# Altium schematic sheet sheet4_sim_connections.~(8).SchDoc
size A3; Author: Mauri Shadi; CompanyName: BFH; DrawnBy: Mauri Shadi; SheetNumber: 2; SheetTotal: 4
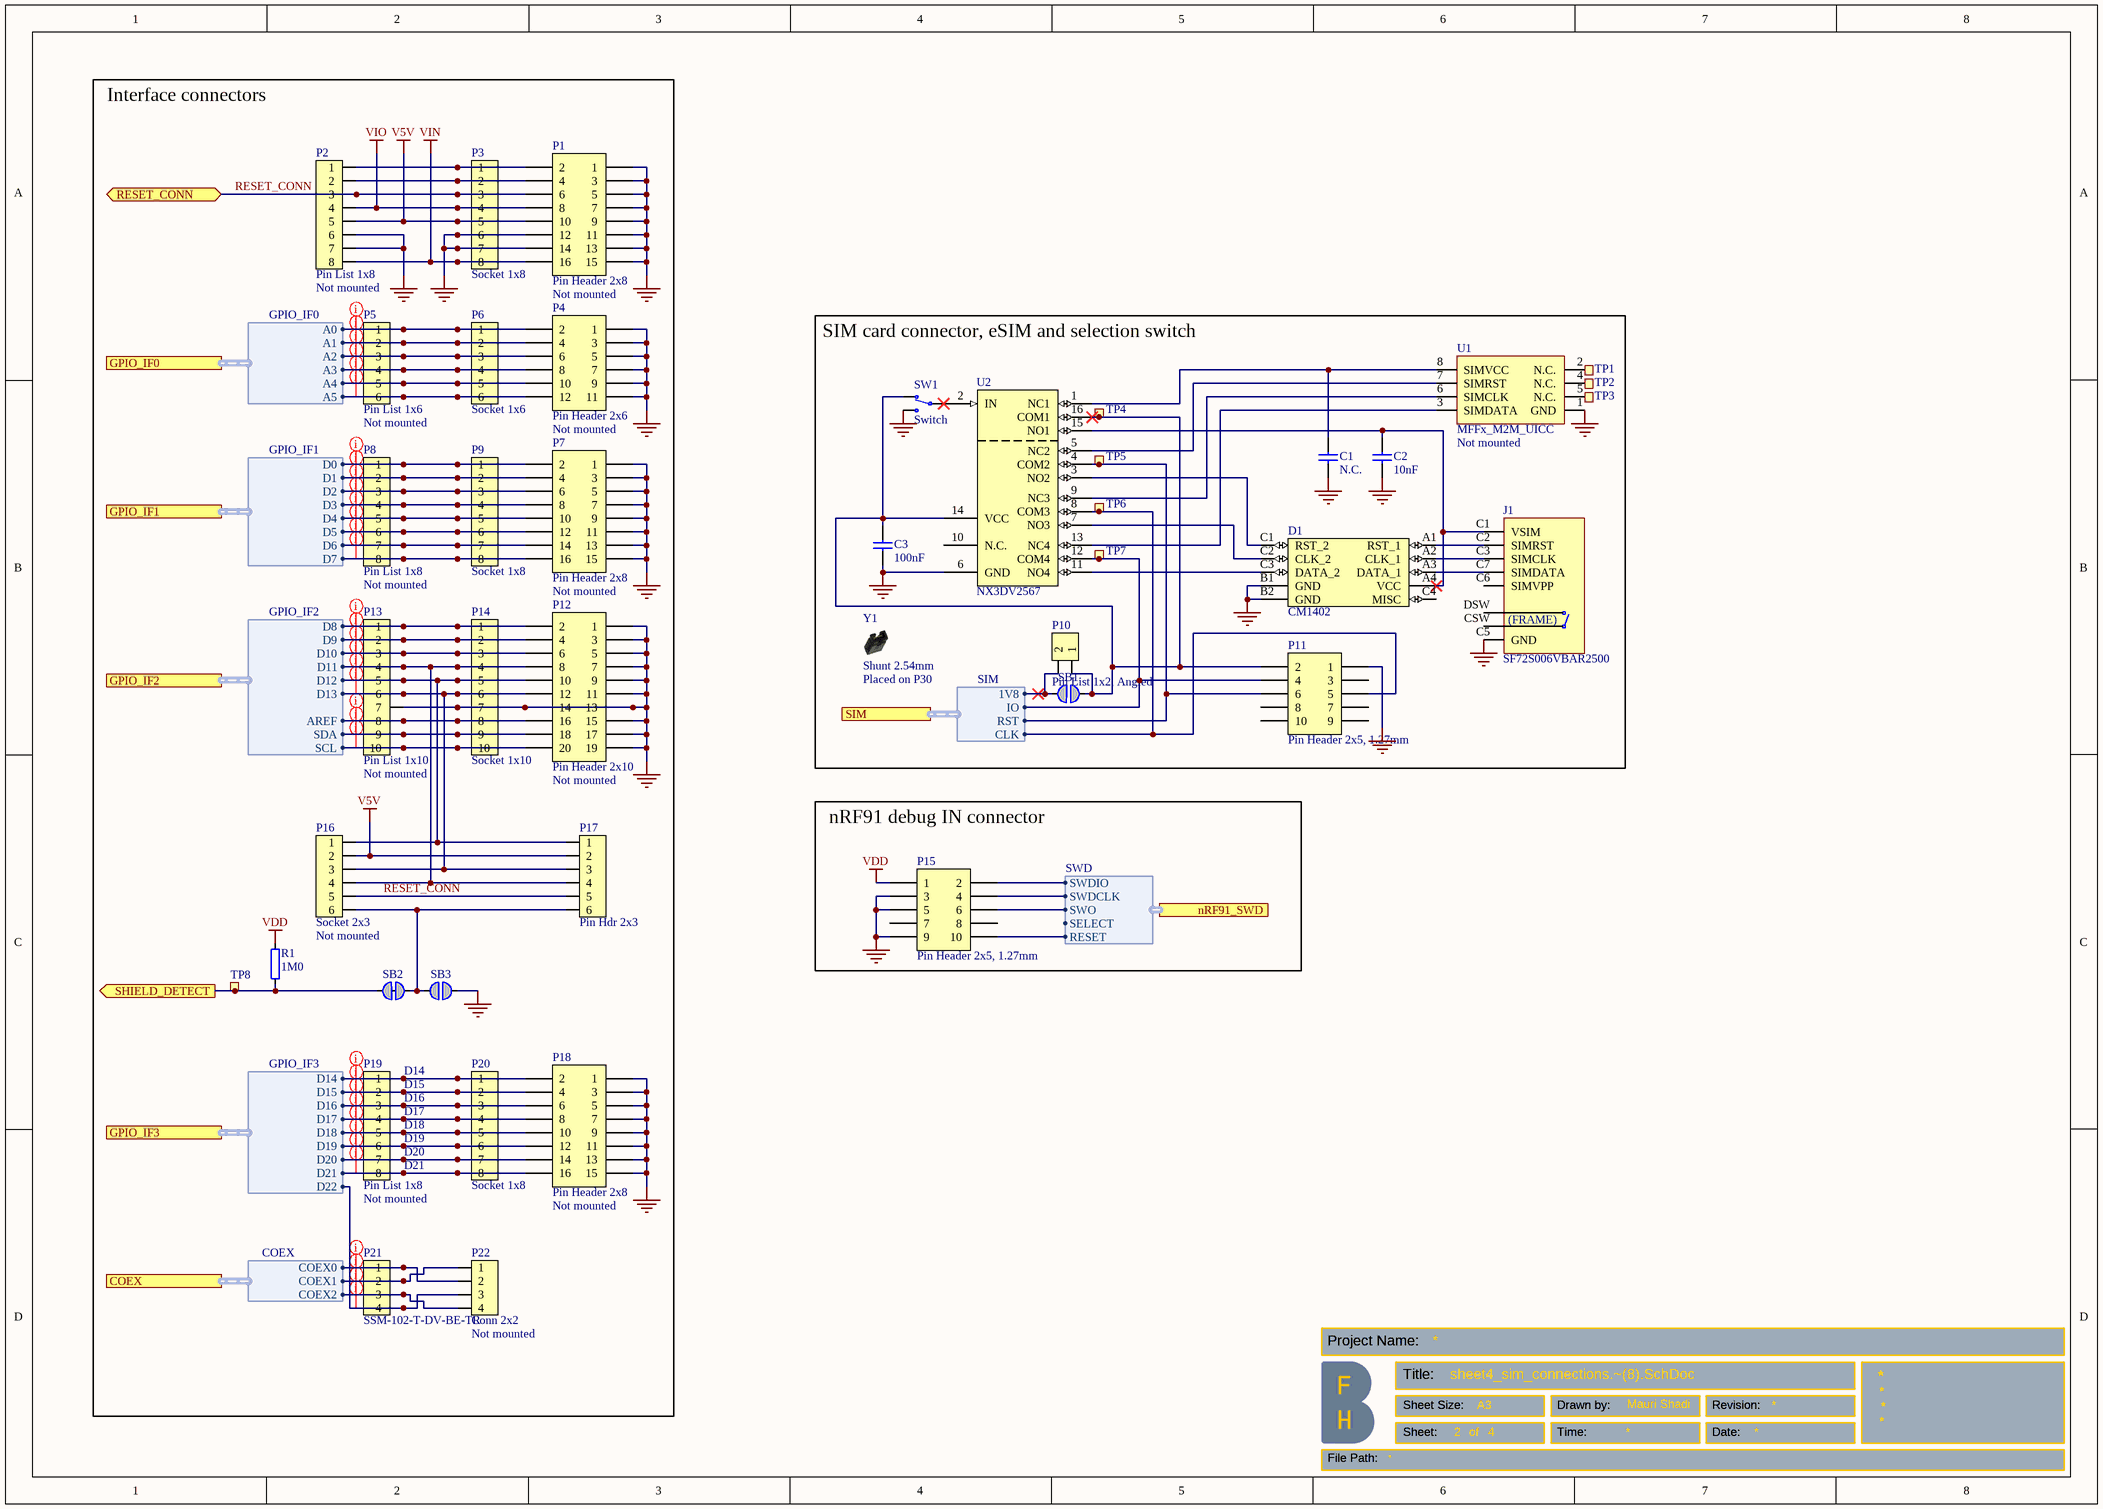
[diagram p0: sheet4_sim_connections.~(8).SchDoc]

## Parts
C1  N.C.  [CAPC0603X03L_C_NC]
C2  10nF  [CAPC0603X03L_C]
C3  100nF  [CAPC0603X03L_C]
D1  CM1402  [CM1402]
J1  SF72S006VBAR2500  [SF72S006VBAR2500]
P1  Pin Header 2x8  Assembly: Not mounted  [HDR_2x8-NC]
P2  Pin List 1x8  Assembly: Not mounted  [LIST_1x8_SMD-NC]
P3  Socket 1x8  [SOCKET_1x8_SMD]
P4  Pin Header 2x6  Assembly: Not mounted  [HDR_2x6-NC]
P5  Pin List 1x6  Assembly: Not mounted  [LIST_1x6_SMD-NC]
P6  Socket 1x6  [SOCKET_1x6_SMD]
P7  Pin Header 2x8  Assembly: Not mounted  [HDR_2x8-NC]
P8  Pin List 1x8  Assembly: Not mounted  [LIST_1x8_SMD-NC]
P9  Socket 1x8  [SOCKET_1x8_SMD]
P10  Pin List 1x2, Angled  [LIST_ANG_1x2-SMD-2.54MM]
P11  Pin Header 2x5, 1.27mm  [HDR_2x5-SMD-1.27mm]
P12  Pin Header 2x10  Assembly: Not mounted  [HDR_2x10-NC]
P13  Pin List 1x10  Assembly: Not mounted  [LIST_1x10_SMD-NC]
P14  Socket 1x10  [SOCKET_1x10_SMD]
P15  Pin Header 2x5, 1.27mm  [HDR_2x5-SMD-1.27mm-K]
P16  Socket 2x3  Assembly: Not mounted  [SOCKET_2x3_SMD-2.54mm-bottom-NC]
P17  Pin Hdr 2x3  [HDR_2x3-SMD]
P18  Pin Header 2x8  Assembly: Not mounted  [HDR_2x8-NC]
P19  Pin List 1x8  Assembly: Not mounted  [LIST_1x8_SMD-NC]
P20  Socket 1x8  [SOCKET_1x8_SMD]
P21  SSM-102-T-DV-BE-TR  [SSM-102-T-DV-BE-TR]
P22  Conn 2x2  Assembly: Not mounted  [HDR_2x2-SMD]
R1  1M0  [RESC0603X03L_C]
SB1  Solderbridge  [Solderbridge]  (value not drawn)  (no BOM)
SB2  Solderbridge  [Solderbridge_Shorted]  (value not drawn)  (net tie, no BOM)
SB3  Solderbridge  [Solderbridge]  (value not drawn)  (no BOM)
SW1  Switch  [CJS-120xA]
TP1  Ø1.0mm,SMD  [TP_SMD_D1.0mm]  (value not drawn)  (no BOM)
TP2  Ø1.0mm,SMD  [TP_SMD_D1.0mm]  (value not drawn)  (no BOM)
TP3  Ø1.0mm,SMD  [TP_SMD_D1.0mm]  (value not drawn)  (no BOM)
TP4  Ø1.5mm,SMD  [TP_SMD_D1.5mm]  (value not drawn)  (no BOM)
TP5  Ø1.5mm,SMD  [TP_SMD_D1.5mm]  (value not drawn)  (no BOM)
TP6  Ø1.5mm,SMD  [TP_SMD_D1.5mm]  (value not drawn)  (no BOM)
TP7  Ø1.5mm,SMD  [TP_SMD_D1.5mm]  (value not drawn)  (no BOM)
TP8  Ø1.5mm,SMD  [TP_SMD_D1.5mm]  (value not drawn)  (no BOM)
U1  MFFx_M2M_UICC  Assembly: Not mounted  [SON127P600X90_HS-8N]
U2  NX3DV2567  [XQFN40P180X260X50-16N]
Y1  Shunt 2.54mm  Assembly: Placed on P30  [Shunt_2.54mm_Horizontal]

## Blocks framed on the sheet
Interface connectors: P1-P9 P12-P14 P16-P22 R1 SB2 SB3 TP8
SIM card connector, eSIM and selection switch: C1-C3 D1 J1 P10 P11 SB1 SW1 TP1-TP7 U1 U2 Y1
nRF91 debug IN connector: P15

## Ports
COEX (harness COEX, see sheet1_connections[3B], sheet2_nRF9160[7C]), GPIO_IF0 (harness GPIO_IF0, see sheet1_connections[3B], sheet2_nRF9160[5B]), GPIO_IF1 (harness GPIO_IF1, see sheet1_connections[3B], sheet2_nRF9160[5C]), GPIO_IF2 (harness GPIO_IF2, see sheet1_connections[3B], sheet2_nRF9160[5C]), GPIO_IF3 (harness GPIO_IF3, see sheet1_connections[3B], sheet2_nRF9160[5C]), nRF91_SWD (harness SWD, see sheet1_connections[3A], sheet2_nRF9160[7C]), RESET_CONN (bidir, see sheet1_connections[4B]), SHIELD_DETECT (out, see sheet1_connections[4A]), SIM (harness SIM, see sheet1_connections[3B], sheet2_nRF9160[7C])

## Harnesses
SWD: SWDIO, SWDCLK, SWO, RESET, SELECT
GPIO_IF0: A0, A1, A2, A3, A4, A5
GPIO_IF1: D0, D1, D2, D3, D4, D5, D6, D7
GPIO_IF2: D8, D9, D10, D11, D12, D13, AREF, SDA, SCL
GPIO_IF3: D14, D15, D16, D17, D18, D19, D20, D21, D22
COEX: COEX0, COEX2, COEX1
SIM: CLK, IO, 1V8, RST

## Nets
GND: C1.1 C2.2 C3.1 D1.B1(GND) D1.B2(GND) J1.0(GND) J1.C5(GND) P1.1 P1.3 P1.5 P1.7 P1.9 P1.11 P1.12 P1.13 P1.14 P1.15 P2.6 P2.7 P3.6 P3.7 P4.1 P4.3 P4.5 P4.7 P4.9 P4.11 P7.1 P7.3 P7.5 P7.7 P7.9 P7.11 P7.13 P7.15 P11.1 P12.1 P12.3 P12.5 P12.7 P12.9 P12.11 P12.13 P12.14 P12.15 P12.17 P12.19 P13.7 P14.7 P15.3 P15.5 P15.9 P18.1 P18.3 P18.5 P18.7 P18.9 P18.11 P18.13 P18.15 SB3.1 SW1.3(N.O) U1.1(GND) U2.6(GND)
V5V: P1.10 P2.5 P3.5 P16.2 P17.2
VDD: P15.1 R1.2
VIN: P1.16 P2.8 P3.8
VIO: P1.8 P2.4 P3.4
RESET_CONN: P1.6 P2.3 P3.3 P16.5 P17.5 ; port RESET_CONN
SHIELD_DETECT: R1.1 SB2.2 TP8.1 ; port SHIELD_DETECT
NetC1_2: C1.2 U1.8(SIMVCC) U2.1(NC1)
NetC2_1: C2.1 D1.A4(VCC) J1.C1(VSIM) U2.15(NO1)
NetC3_2: C3.2 P10.1 P11.2 SB1.2 SW1.1(N.C) TP4.1 U2.14(VCC) U2.16(COM1)
NetD1_A1: D1.A1(RST_1) J1.C2(SIMRST)
NetD1_A2: D1.A2(CLK_1) J1.C3(SIMCLK)
NetD1_A3: D1.A3(DATA_1) J1.C7(SIMDATA)
NetD1_C1: D1.C1(RST_2) U2.3(NO2)
NetD1_C2: D1.C2(CLK_2) U2.7(NO3)
NetD1_C3: D1.C3(DATA_2) U2.11(NO4)
NetP1_2: P1.2 P2.1 P3.1
NetP1_4: P1.4 P2.2 P3.2
NetP4_2: P4.2 P5.1 P6.1 ; port GPIO_IF0.A0
NetP4_4: P4.4 P5.2 P6.2 ; port GPIO_IF0.A1
NetP4_6: P4.6 P5.3 P6.3 ; port GPIO_IF0.A2
NetP4_8: P4.8 P5.4 P6.4 ; port GPIO_IF0.A3
NetP4_10: P4.10 P5.5 P6.5 ; port GPIO_IF0.A4
NetP4_12: P4.12 P5.6 P6.6 ; port GPIO_IF0.A5
NetP7_2: P7.2 P8.1 P9.1 ; port GPIO_IF1.D0
NetP7_4: P7.4 P8.2 P9.2 ; port GPIO_IF1.D1
NetP7_6: P7.6 P8.3 P9.3 ; port GPIO_IF1.D2
NetP7_8: P7.8 P8.4 P9.4 ; port GPIO_IF1.D3
NetP7_10: P7.10 P8.5 P9.5 ; port GPIO_IF1.D4
NetP7_12: P7.12 P8.6 P9.6 ; port GPIO_IF1.D5
NetP7_14: P7.14 P8.7 P9.7 ; port GPIO_IF1.D6
NetP7_16: P7.16 P8.8 P9.8 ; port GPIO_IF1.D7
NetP10_2: P10.2 SB1.1 ; port SIM.1V8
NetP11_4: P11.4 TP7.1 U2.12(COM4) ; port SIM.IO
NetP11_5: P11.5 TP6.1 U2.8(COM3) ; port SIM.CLK
NetP11_6: P11.6 TP5.1 U2.4(COM2) ; port SIM.RST
NetP12_2: P12.2 P13.1 P14.1 ; port GPIO_IF2.D8
NetP12_4: P12.4 P13.2 P14.2 ; port GPIO_IF2.D9
NetP12_6: P12.6 P13.3 P14.3 ; port GPIO_IF2.D10
NetP12_8: P12.8 P13.4 P14.4 P16.4 P17.4 ; port GPIO_IF2.D11
NetP12_10: P12.10 P13.5 P14.5 P16.1 P17.1 ; port GPIO_IF2.D12
NetP12_12: P12.12 P13.6 P14.6 P16.3 P17.3 ; port GPIO_IF2.D13
NetP12_16: P12.16 P13.8 P14.8 ; port GPIO_IF2.AREF
NetP12_18: P12.18 P13.9 P14.9 ; port GPIO_IF2.SDA
NetP12_20: P12.20 P13.10 P14.10 ; port GPIO_IF2.SCL
NetP15_2: P15.2 ; port nRF91_SWD.SWDIO
NetP15_4: P15.4 ; port nRF91_SWD.SWDCLK
NetP15_6: P15.6 ; port nRF91_SWD.SWO
NetP15_10: P15.10 ; port nRF91_SWD.RESET
NetP16_6: P16.6 P17.6 SB2.1 SB3.2
NetP18_2: P18.2 P19.1 P20.1 ; port GPIO_IF3.D14
NetP18_4: P18.4 P19.2 P20.2 ; port GPIO_IF3.D15
NetP18_6: P18.6 P19.3 P20.3 ; port GPIO_IF3.D16
NetP18_8: P18.8 P19.4 P20.4 ; port GPIO_IF3.D17
NetP18_10: P18.10 P19.5 P20.5 ; port GPIO_IF3.D18
NetP18_12: P18.12 P19.6 P20.6 ; port GPIO_IF3.D19
NetP18_14: P18.14 P19.7 P20.7 ; port GPIO_IF3.D20
NetP18_16: P18.16 P19.8 P20.8 ; port GPIO_IF3.D21
NetP21_1: P21.1 P22.2 ; port COEX.COEX0
NetP21_2: P21.2 P22.1 ; port COEX.COEX1
NetP21_3: P21.3 P22.4 ; port COEX.COEX2
NetP21_4: P21.4 P22.3 ; port GPIO_IF3.D22
NetSW1_2: SW1.2(COM) U2.2(IN)
NetTP1_1: TP1.1 U1.2(N.C.)
NetTP2_1: TP2.1 U1.4(N.C.)
NetTP3_1: TP3.1 U1.5(N.C.)
NetU1_3: U1.3(SIMDATA) U2.13(NC4)
NetU1_6: U1.6(SIMCLK) U2.9(NC3)
NetU1_7: U1.7(SIMRST) U2.5(NC2)

Not connected (* = marked no-connect by the designer): D1 C4(MISC); J1 C6(SIMVPP) CSW DSW; P11 3 7 8 9 10; P15 7 8; U2 10(N.C.)

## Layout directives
net class GPIO: NetP4_2, NetP4_4, NetP4_6, NetP4_8, NetP4_10, NetP4_12, NetP7_2, NetP7_4, NetP7_6, NetP7_8, NetP7_10, NetP7_12, NetP7_14, NetP7_16, NetP12_2, NetP12_4, NetP12_6, NetP12_8, NetP12_10, NetP12_12, NetP12_16, NetP12_18, NetP12_20, NetP18_2, NetP18_4, NetP18_6, NetP18_8, NetP18_10, NetP18_12, NetP18_14, NetP18_16, NetP21_1, NetP21_2, NetP21_3, NetP21_4

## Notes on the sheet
- (near P19) D14
- (near P19) D15
- (near P19) D16
- (near P19) D17
- (near P19) D18
- (near P19) D19
- (near P19) D20
- (near P19) D21

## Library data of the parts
C1 = C0201-N.C.: Not mounted; Manufacturer: N.A.; Note: Chip Cap; Assembly: Not mounted; Pad Count: 2
C2 = C0201-10n: Capacitor, X7R, ±10%; Manufacturer: N.A.; Part number IPS: 00000003480; Note: 10V; Pad Count: 2
C3 = C0201-100n: Capacitor, X5R, ±10%; Manufacturer: N.A.; Part number IPS: 00000001248, 00000002505; Note: 16V; Pad Count: 2
D1 = CM1402: EMI Network Filter Arrays SIM CARD EMI FILTER WITH ESD PROTECTION; Manufacturer: ON Semiconductor; Manufacturer Part Number: CM1402-03CP; Part number IPS: 00000009949; Note: N.A.; Pad Count: 10
J1 = SF72S006VBAR2500: n 8 (6 + 2) Position Card Connector NANO SIM Surface Mount, Right Angle Gold; Manufacturer: JAE Electronics; Part number IPS: 00000009956; Note: N.A.; Pad Count: 8
P1 P7 P18 = Pin Header 2x8, N.C.: Pin Header 2x8, 2.54mm (100mil); Manufacturer: N.A.; Pad Count: 16
P2 P8 P19 = Pin List 1x8 SMD, N.C.: Pin List 1x8, 2.54mm (100mil), SMD; Manufacturer: W-CON; Manufacturer Part Number: 1125-1108S0M116R2; Note: N.A.; Artikkelnr Noca: 55010006; Pad Count: 8
P3 P9 P20 = Socket 1x8 SMD: Socket 1x8, 2.54mm (100mil), SMD; Manufacturer: W-CON; Manufacturer Part Number: 2171-108MS0CUNR1; Part number IPS: 00000009963; Note: N.A.; Artikkelnr Noca: 55030002; Pad Count: 8
P4 = Pin Header 2x6, N.C.: Pin Header 2x6, 2.54mm (100mil); Manufacturer: N.A.; Pad Count: 12
P5 = Pin List 1x6 SMD, N.C.: Pin List 1x6, 2.54mm (100mil), SMD; Manufacturer: W-CON; Manufacturer Part Number: 1125-1106S0M116R2; Note: N.A.; Artikkelnr Noca: 55010026; Pad Count: 6
P6 = Socket 1x6 SMD: Socket 1x6, 2.54mm (100mil), SMD; Manufacturer: W-CON; Manufacturer Part Number: 2171-106MS0CUNR1; Part number IPS: 00000009964; Note: N.A.; Artikkelnr Noca: 55030001; Pad Count: 6
P10 = Pin List Ang 1x2 SMD, 2.54mm: Pin List 1x2, 2.54mm (100mil), Right Angled, SMD; Manufacturer: W-CON; Manufacturer Part Number: 1125B-1102S0Z135R2; Part number IPS: 00000009972; Note: N.A.; Artikkelnr Noca: 55010023; Pad Count: 2
P11 = Pin Header 2x5 SMD, 1.27mm: Pin Header 2x5, 1.27mm (50mil), SMD; Manufacturer: W-CON; Manufacturer Part Number: 1325-1205S0M078R1; Part number IPS: 00000009970; Note: N.A.; Artikkelnr Noca: 55019196; Pad Count: 10
P12 = Pin Header 2x10, N.C.: Pin Header 2x10, 2.54mm (100mil); Manufacturer: N.A.; Pad Count: 20
P13 = Pin List 1x10 SMD, N.C.: Pin List 1x10, 2.54mm (100mil), SMD; Manufacturer: W-CON; Manufacturer Part Number: 1125-1110S0M116R2; Note: N.A.; Artikkelnr Noca: 55010028; Pad Count: 10
P14 = Socket 1x10 SMD: Socket 1x10, 2.54mm (100mil), SMD; Manufacturer: W-CON; Manufacturer Part Number: 2171-110MS0CUNR1; Part number IPS: 00000009965; Note: N.A.; Artikkelnr Noca: 55030004; Pad Count: 10
P15 = Pin Header 2x5 SMD, 1.27mm, KS: Pin Header 2x5, 1.27mm (50mil), SMD, Keying Shroud; Manufacturer: W-CON; Manufacturer Part Number: 3132-10MS0BK00R1; Part number IPS: 00000009968; Note: N.A.; Artikkelnr Noca: 55010009; Pad Count: 10
P16 = Socket 2x3 SMD Bottom, N.C.: Socket 2x3, 2.54mm (100mil), SMD; Manufacturer: W-CON; Manufacturer Part Number: 2171-203MS0CUNR1; Note: N.A.; Artikkelnr Noca: 55030010; Pad Count: 6
P17 = Pin Header 2x3 SMD: Pin Header 2x3, 2.54mm (100mil) SMD; Manufacturer: W-CON; Manufacturer Part Number: 1125-1203S0M116R1; Part number IPS: 00000009966; Part number Norautron: N.A.; Artikkelnr Noca: 55010007; Pad Count: 6
P21 = 2171-202MSNCUNR1: .025 SOCKET STRIPS; Manufacturer: W-CON; Part number IPS: 00000001417; Note: N.A.; Pad Count: 4
P22 = HDR_2x2_SMD_GOLD: CONN HEADER 4POS .100" VERT 15AU; Manufacturer: Molex; Note: SMD, gold plating; Artikkelnr Noca: N.A.; Pad Count: 4
R1 = R0201-1M0: Resistor, ±1%, 0.05W; Manufacturer: N.A.; Part number IPS: 00000001418; Note: Chip Res 1%; Pad Count: 2
SB1 SB3 = Solderbridge: Manufacturer: N.A.; Pad Count: 2
SB2 = Solderbridge Shorted: Shorted Solderbridge; Manufacturer: N.A.; Pad Count: 2
SW1 = CJS-1200TA: SMD slide Switch (ON-ON); Manufacturer: Copal Electronics Inc; Part number IPS: 00000009982; Note: N.A.; Artikkelnr Noca: 50019068; Pad Count: 3
TP1-TP3 = TP_SMD_Ø1.0MM: 1.0mm circular SMD testpad; Manufacturer: Nordic Semiconductor; Manufacturer Part Number: N.A.; Pad Count: 1
TP4-TP8 = TP_SMD_Ø1.5MM: 1.5mm circular SMD testpad; Manufacturer: Nordic Semiconductor; Manufacturer Part Number: N.A.; Pad Count: 1
U1 = M2M_UICC: M2M UICC SIM Card; Manufacturer: N.A.; Pad Count: 8
U2 = NX3DV2567GU: Low-ohmic four-pole double-throw analog switch; Manufacturer: NXP Semiconductors; Part number IPS: 00000007816; Note: N.A.; Artikkelnr Noca: 15079317; Pad Count: 16
Y1 = SHUNT JUMPER 2.54mm BLACK GOLD Horizontal (obsolete): Shunt Jumper 2.54mm Black; Manufacturer: N.A.; Part number IPS: 00000001916; Note: SHUNT JUMPER .1" BLACK GOLD, h=6.00mm, w=5.00mm; Artikkelnr Noca: 56099001; Pad Count: 2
